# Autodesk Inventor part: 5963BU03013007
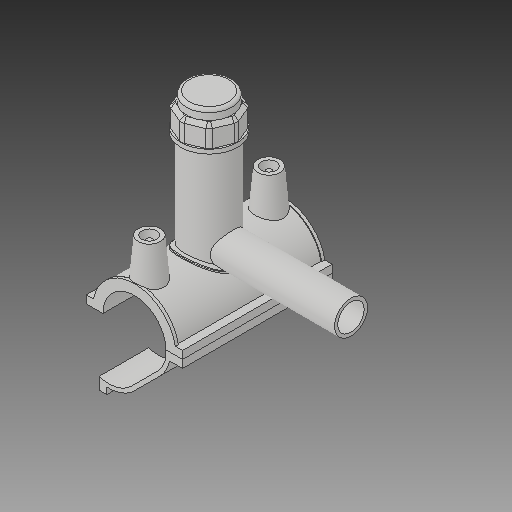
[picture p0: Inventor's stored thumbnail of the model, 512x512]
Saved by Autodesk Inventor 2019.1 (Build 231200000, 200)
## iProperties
Created: 2017-07
Part Number: 5963BU03013007
Material: Generic
Description: PLASSON TAPPING SADDLE 1 1/4''IPS x 3/4''CTS
Document SubType Name: Modeling
Designer: KIM
Mass: 1712.7 g
Surface Area: 2671.49 cm^2
Volume: 1712.7 cm^3
Density: 1 g/cm^3
Appearance: Default
Author: KIM
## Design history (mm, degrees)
derived "5963B.ipt"
feature "Solid1::5963B.ipt"
feature "Solid2::5963B.ipt"
feature "Solid4::5963B.ipt"
feature "Solid5::5963B.ipt"
tag "TaggingFeature1"
body "Solid1"
body "Solid2"
other parameters: "d_" = 42.1, "B_" = 64.516, "L_" = 100.076, "d_t" = 6, "H_2" = 93.726, "H_1" = 9.906, "d_1" = 22.1, "H_" = 94.996, "d1" = 54.73, "d148" = 0.6315, "d160" = 0.6315, "d169" = 3.2805, "d192" = 6.1236, "d0" = 42.1, "d2" = 64.516, "d3" = 10.525, "d4" = 100.076, "d5" = 0, "d6" = 0.1, "d8" = 0, "d19" = 6, "d20" = 6, "d21" = 60.0456, "d23" = 0, "d24" = 30.0228, "d26" = 0, "d29" = 3, "d30" = 14.03333, "d31" = 6, "d32" = 0, "d33" = 0, "d34" = 0.6, "d40" = 28.4596, "d41" = 37.89, "d43" = 0, "d45" = 0, "d47" = 87.4106, "d70" = 15, "d72" = 0, "d73" = 6, "d75" = 5, "d76" = 0, "d77" = 2.105, "d78" = 51.05, "d79" = 15, "d80" = 40.0304, "d82" = 5 deg, "d84" = 4, "d85" = 14, "d86" = 0, "d87" = 3, "d88" = 0, "d89" = 1, "d90" = 1, "d91" = 80.0608, "d92" = 0, "d93" = 0.5, "d94" = 22.15789, "d96" = 55.8246, "d97" = 2.00152, "d98" = 0, "d102" = 0.421, "d120" = 140 deg, "d121" = 24.228, "d122" = 20 deg, "d123" = 109.46, "d124" = 32.838, "d126" = 0, "d143" = 43.363, "d145" = 9.71538, "d149" = 0.6315, "d150" = 10.68692, "d153" = 100.076, "d154" = 0, "d156" = 27.365, "d157" = 160 deg, "d159" = 2.526, "d161" = 0.6315, "d162" = 60.0456, "d163" = 0, "d164" = 21.05, "d167" = 4.21, "d168" = 26.69756, "d170" = 3.2805, "d172" = 0, "d173" = 1, "d175" = 21.05, "d176" = 20 deg, "d177" = 2.947, "d178" = 12.63, "d180" = 0, "d183" = 5.052, "d184" = 2.3576, "d185" = 32.5247, "d186" = 32.5247, "d187" = 27.365, "d188" = 3.789, "d189" = 2.947, "d190" = 0, "d191" = 41.0475, "d193" = 6.1236, "d194" = 3.50266, "d195" = 90 deg, "d197" = 0, "d199" = 0, "d200" = 6.315, "d202" = 0, "d203" = 93.726, "d204" = 35.9955, "d205" = 26.523, "d206" = 32.2065, "d207" = 70.2945, "d208" = 73.10628, "d209" = 87.16518, "d210" = 32.5854, "d211" = 37.89, "d212" = 30.312, "d213" = -1.0296, "d216" = 0, "d217" = 4.21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
